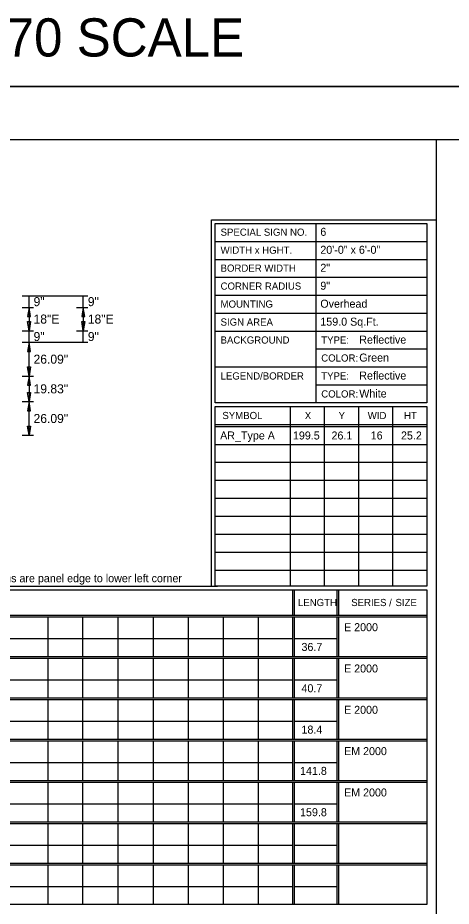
# Model space of a CAD drawing. Extents: x 2149934 to 2150188, y 145113 to 145238.
# Drawn here: x 2150108.5 to 2150136.4, y 145167.1 to 145224.4 of the extents above; entities that cross this region are included whole.
import ezdxf

# ---------------------------------------------------------------- set-up
doc = ezdxf.new("R2010")
doc.units = 0
for name, color, linetype in [('BORDER', 7, 'Continuous'), ('GSDIMS', 7, 'Continuous'), ('GSSHT', 7, 'Continuous'), ('Level 1', 7, 'Continuous'), ('PDF', 7, 'Continuous'), ('TEXT', 7, 'Continuous')]:
    doc.layers.add(name, color=color, linetype=linetype)

msp = doc.modelspace()

# ---------------------------------------------------------------- linework, layer by layer
at = {"layer": 'BORDER'}
for p, q in [((2150010.458, 145219.948), (2150174.061, 145219.948)), ((2150171.536, 145216.512), (2150017.557, 145216.512))]:
    msp.add_line(p, q, dxfattribs=at)
at = {"layer": 'GSDIMS'}
for p, q in [((2150108.758, 145206.445), (2150109.487, 145206.445)), ((2150108.758, 145206.445), (2150112.258, 145206.445)), ((2150109.195, 145205.695), (2150109.195, 145206.445)), ((2150112.258, 145206.445), (2150112.987, 145206.445)), ((2150112.695, 145205.695), (2150112.695, 145206.445)), ((2150108.758, 145205.695), (2150109.487, 145205.695)), ((2150108.758, 145205.695), (2150109.487, 145205.695)), ((2150109.195, 145205.695), (2150109.195, 145204.195)), ((2150112.258, 145205.695), (2150112.987, 145205.695)), ((2150112.258, 145205.695), (2150112.987, 145205.695)), ((2150112.695, 145205.695), (2150112.695, 145204.195)), ((2150108.758, 145204.195), (2150109.487, 145204.195)), ((2150108.758, 145204.195), (2150109.487, 145204.195)), ((2150109.195, 145203.445), (2150109.195, 145204.195)), ((2150112.258, 145204.195), (2150112.987, 145204.195)), ((2150112.258, 145204.195), (2150112.987, 145204.195)), ((2150112.695, 145203.445), (2150112.695, 145204.195)), ((2150108.758, 145203.445), (2150109.487, 145203.445)), ((2150108.758, 145203.445), (2150108.758, 145203.445)), ((2150108.758, 145203.445), (2150109.487, 145203.445)), ((2150108.758, 145203.445), (2150112.258, 145203.445)), ((2150109.195, 145201.271), (2150109.195, 145203.445)), ((2150112.258, 145203.445), (2150112.987, 145203.445)), ((2150108.758, 145201.271), (2150109.487, 145201.271)), ((2150108.758, 145201.271), (2150109.487, 145201.271)), ((2150109.195, 145201.271), (2150109.195, 145199.618)), ((2150108.758, 145199.618), (2150109.487, 145199.618)), ((2150108.758, 145199.618), (2150109.487, 145199.618)), ((2150109.195, 145197.445), (2150109.195, 145199.618)), ((2150108.758, 145197.445), (2150109.487, 145197.445)), ((2150108.758, 145197.445), (2150108.758, 145197.445))]:
    msp.add_line(p, q, dxfattribs=at)
for points in [[(2150109.195, 145205.695), (2150109.098, 145205.112), (2150109.293, 145205.112)], [(2150112.695, 145205.695), (2150112.598, 145205.112), (2150112.793, 145205.112)], [(2150109.195, 145204.195), (2150109.098, 145204.778), (2150109.293, 145204.778)], [(2150112.695, 145204.195), (2150112.598, 145204.778), (2150112.793, 145204.778)], [(2150109.195, 145203.445), (2150109.098, 145202.862), (2150109.293, 145202.862)], [(2150109.195, 145201.271), (2150109.098, 145201.854), (2150109.293, 145201.854)], [(2150109.195, 145201.271), (2150109.098, 145200.688), (2150109.293, 145200.688)], [(2150109.195, 145199.618), (2150109.098, 145200.202), (2150109.293, 145200.202)], [(2150109.195, 145199.618), (2150109.098, 145199.035), (2150109.293, 145199.035)], [(2150109.195, 145197.445), (2150109.098, 145198.028), (2150109.293, 145198.028)]]:
    msp.add_lwpolyline(points, close=True, dxfattribs=at)
at = {"layer": 'Level 1'}
for p, q in [((2150135.447, 145216.512), (2150135.447, 145124.606)), ((2150120.969, 145211.34), (2150135.447, 145211.34)), ((2150127.694, 145211.108), (2150127.694, 145199.537)), ((2150121.201, 145209.949), (2150134.843, 145209.949)), ((2150121.201, 145208.789), (2150134.843, 145208.789)), ((2150121.201, 145207.653), (2150134.843, 145207.653)), ((2150121.201, 145206.494), (2150134.843, 145206.494)), ((2150121.201, 145205.334), (2150134.843, 145205.334)), ((2150121.201, 145204.175), (2150134.843, 145204.175)), ((2150127.694, 145203.015), (2150134.843, 145203.015)), ((2150121.201, 145201.856), (2150134.843, 145201.856)), ((2150127.694, 145200.696), (2150134.843, 145200.696)), ((2150121.201, 145187.705), (2150121.201, 145199.305)), ((2150121.201, 145199.305), (2150134.843, 145199.305)), ((2150126.031, 145199.299), (2150126.031, 145198.14)), ((2150128.234, 145199.299), (2150128.234, 145198.14)), ((2150130.437, 145199.299), (2150130.437, 145198.14)), ((2150132.64, 145199.299), (2150132.64, 145198.14)), ((2150134.843, 145199.305), (2150134.843, 145187.705)), ((2150121.201, 145198.14), (2150134.843, 145198.14)), ((2150121.201, 145198.024), (2150134.843, 145198.024)), ((2150126.031, 145198.14), (2150126.031, 145187.705)), ((2150128.234, 145198.14), (2150128.234, 145187.705)), ((2150130.437, 145198.14), (2150130.437, 145187.705)), ((2150132.64, 145198.14), (2150132.64, 145187.705)), ((2150121.201, 145196.864), (2150134.843, 145196.864)), ((2150121.201, 145195.705), (2150134.843, 145195.705)), ((2150121.201, 145194.545), (2150134.843, 145194.545)), ((2150121.201, 145193.386), (2150134.843, 145193.386)), ((2150121.201, 145192.227), (2150134.843, 145192.227)), ((2150121.201, 145191.067), (2150134.843, 145191.067)), ((2150121.201, 145189.908), (2150134.843, 145189.908)), ((2150121.201, 145188.748), (2150134.843, 145188.748)), ((2150076.316, 145187.705), (2150121.342, 145187.705)), ((2150134.843, 145187.705), (2150121.201, 145187.705)), ((2150126.185, 145187.473), (2150126.185, 145185.849)), ((2150126.301, 145187.473), (2150126.301, 145185.849)), ((2150129.048, 145187.473), (2150129.048, 145185.849)), ((2150129.164, 145187.473), (2150129.164, 145185.849)), ((2150076.548, 145185.849), (2150134.843, 145185.849)), ((2150076.548, 145185.733), (2150134.843, 145185.733)), ((2150110.405, 145185.733), (2150110.405, 145183.183)), ((2150112.654, 145185.733), (2150112.654, 145183.183)), ((2150114.927, 145185.733), (2150114.927, 145183.183)), ((2150117.199, 145185.733), (2150117.199, 145183.183)), ((2150119.449, 145185.733), (2150119.449, 145183.183)), ((2150121.721, 145185.733), (2150121.721, 145183.183)), ((2150123.97, 145185.733), (2150123.97, 145183.183)), ((2150126.185, 145185.733), (2150126.185, 145183.183)), ((2150126.301, 145185.733), (2150126.301, 145183.183)), ((2150129.048, 145185.733), (2150129.048, 145183.183)), ((2150129.164, 145185.733), (2150129.164, 145183.183)), ((2150076.548, 145184.342), (2150126.185, 145184.342)), ((2150126.301, 145184.342), (2150129.048, 145184.342)), ((2150076.548, 145183.183), (2150134.843, 145183.183)), ((2150076.548, 145183.067), (2150134.843, 145183.067)), ((2150110.405, 145183.067), (2150110.405, 145180.516)), ((2150112.654, 145183.067), (2150112.654, 145180.516)), ((2150114.927, 145183.067), (2150114.927, 145180.516)), ((2150117.199, 145183.067), (2150117.199, 145180.516)), ((2150119.449, 145183.067), (2150119.449, 145180.516)), ((2150121.721, 145183.067), (2150121.721, 145180.516)), ((2150123.97, 145183.067), (2150123.97, 145180.516)), ((2150126.185, 145183.067), (2150126.185, 145180.516)), ((2150126.301, 145183.067), (2150126.301, 145180.516)), ((2150129.048, 145183.067), (2150129.048, 145180.516)), ((2150129.164, 145183.067), (2150129.164, 145180.516)), ((2150076.548, 145181.675), (2150126.185, 145181.675)), ((2150126.301, 145181.675), (2150129.048, 145181.675)), ((2150076.548, 145180.516), (2150134.843, 145180.516)), ((2150076.548, 145180.4), (2150134.843, 145180.4)), ((2150110.405, 145180.4), (2150110.405, 145177.849)), ((2150112.654, 145180.4), (2150112.654, 145177.849)), ((2150114.927, 145180.4), (2150114.927, 145177.849)), ((2150117.199, 145180.4), (2150117.199, 145177.849)), ((2150119.449, 145180.4), (2150119.449, 145177.849)), ((2150121.721, 145180.4), (2150121.721, 145177.849)), ((2150123.97, 145180.4), (2150123.97, 145177.849)), ((2150126.185, 145180.4), (2150126.185, 145177.849)), ((2150126.301, 145180.4), (2150126.301, 145177.849)), ((2150129.048, 145180.4), (2150129.048, 145177.849)), ((2150129.164, 145180.4), (2150129.164, 145177.849)), ((2150076.548, 145179.008), (2150126.185, 145179.008)), ((2150126.301, 145179.008), (2150129.048, 145179.008)), ((2150076.548, 145177.849), (2150134.843, 145177.849)), ((2150076.548, 145177.733), (2150134.843, 145177.733)), ((2150110.405, 145177.733), (2150110.405, 145175.182)), ((2150112.654, 145177.733), (2150112.654, 145175.182)), ((2150114.927, 145177.733), (2150114.927, 145175.182)), ((2150117.199, 145177.733), (2150117.199, 145175.182)), ((2150119.449, 145177.733), (2150119.449, 145175.182)), ((2150121.721, 145177.733), (2150121.721, 145175.182)), ((2150123.97, 145177.733), (2150123.97, 145175.182)), ((2150126.185, 145177.733), (2150126.185, 145175.182)), ((2150126.301, 145177.733), (2150126.301, 145175.182)), ((2150129.048, 145177.733), (2150129.048, 145175.182)), ((2150129.164, 145177.733), (2150129.164, 145175.182)), ((2150076.548, 145176.342), (2150126.185, 145176.342)), ((2150126.301, 145176.342), (2150129.048, 145176.342)), ((2150076.548, 145175.182), (2150134.843, 145175.182)), ((2150076.548, 145175.066), (2150134.843, 145175.066)), ((2150110.405, 145175.066), (2150110.405, 145172.515)), ((2150112.654, 145175.066), (2150112.654, 145172.515)), ((2150114.927, 145175.066), (2150114.927, 145172.515)), ((2150117.199, 145175.066), (2150117.199, 145172.515)), ((2150119.449, 145175.066), (2150119.449, 145172.515)), ((2150121.721, 145175.066), (2150121.721, 145172.515)), ((2150123.97, 145175.066), (2150123.97, 145172.515)), ((2150126.185, 145175.066), (2150126.185, 145172.515)), ((2150126.301, 145175.066), (2150126.301, 145172.515)), ((2150129.048, 145175.066), (2150129.048, 145172.515)), ((2150129.164, 145175.066), (2150129.164, 145172.515)), ((2150076.548, 145173.675), (2150126.185, 145173.675)), ((2150126.301, 145173.675), (2150129.048, 145173.675)), ((2150076.548, 145172.515), (2150134.843, 145172.515)), ((2150076.548, 145172.399), (2150134.843, 145172.399)), ((2150110.405, 145172.399), (2150110.405, 145169.849)), ((2150112.654, 145172.399), (2150112.654, 145169.849)), ((2150114.927, 145172.399), (2150114.927, 145169.849)), ((2150117.199, 145172.399), (2150117.199, 145169.849)), ((2150119.449, 145172.399), (2150119.449, 145169.849)), ((2150121.721, 145172.399), (2150121.721, 145169.849)), ((2150123.97, 145172.399), (2150123.97, 145169.849)), ((2150126.185, 145172.399), (2150126.185, 145169.849)), ((2150126.301, 145172.399), (2150126.301, 145169.849)), ((2150129.048, 145172.399), (2150129.048, 145169.849)), ((2150129.164, 145172.399), (2150129.164, 145169.849)), ((2150076.548, 145171.008), (2150126.185, 145171.008)), ((2150126.301, 145171.008), (2150129.048, 145171.008)), ((2150076.548, 145169.849), (2150134.843, 145169.849)), ((2150076.548, 145169.733), (2150134.843, 145169.733)), ((2150110.405, 145169.733), (2150110.405, 145167.182)), ((2150112.654, 145169.733), (2150112.654, 145167.182)), ((2150114.927, 145169.733), (2150114.927, 145167.182)), ((2150117.199, 145169.733), (2150117.199, 145167.182)), ((2150119.449, 145169.733), (2150119.449, 145167.182)), ((2150121.721, 145169.733), (2150121.721, 145167.182)), ((2150123.97, 145169.733), (2150123.97, 145167.182)), ((2150126.185, 145169.733), (2150126.185, 145167.182)), ((2150126.301, 145169.733), (2150126.301, 145167.182)), ((2150129.048, 145169.733), (2150129.048, 145167.182)), ((2150129.164, 145169.733), (2150129.164, 145167.182)), ((2150076.548, 145168.341), (2150126.185, 145168.341)), ((2150126.301, 145168.341), (2150129.048, 145168.341))]:
    msp.add_line(p, q, dxfattribs=at)
msp.add_lwpolyline([(2150120.969, 145187.705), (2150120.969, 145211.34)], dxfattribs=at)
for points in [[(2150121.201, 145211.108), (2150134.843, 145211.108), (2150134.843, 145199.537), (2150121.201, 145199.537)], [(2150076.548, 145187.473), (2150134.843, 145187.473), (2150134.843, 145167.182), (2150076.548, 145167.182)]]:
    msp.add_lwpolyline(points, close=True, dxfattribs=at)
at = {"layer": 'PDF'}
msp.add_lwpolyline([(2150010.458, 145114.088), (2150174.061, 145114.088), (2150174.061, 145219.948), (2150010.458, 145219.948)], close=True, dxfattribs=at)

# ---------------------------------------------------------------- texts
at = {"layer": 'GSDIMS'}
for s, p in [('9"', (2150109.487, 145205.778)), ('9"', (2150112.987, 145205.778)), ('18"E', (2150109.487, 145204.653)), ('18"E', (2150112.987, 145204.653)), ('9"', (2150109.487, 145203.528)), ('9"', (2150112.987, 145203.528)), ('26.09"', (2150109.487, 145202.066)), ('19.83"', (2150109.487, 145200.153)), ('26.09"', (2150109.487, 145198.24))]:
    msp.add_text(s, height=0.5833, dxfattribs=at).set_placement(p)
at = {"layer": 'GSSHT'}
for s, height, p in [('6', 0.517, (2150127.983, 145210.315)), ('Overhead', 0.5165, (2150127.983, 145205.679))]:
    msp.add_text(s, height=height, dxfattribs=at).set_placement(p)
at = {"layer": 'Level 1'}
for s, height, p in [('SPECIAL SIGN NO.', 0.46374, (2150121.549, 145210.32)), ('WIDTH x HGHT.', 0.46374, (2150121.549, 145209.16)), ('20\'-0" x 6\'-0"', 0.51652, (2150127.983, 145209.156)), ('BORDER WIDTH', 0.46374, (2150121.549, 145208.001)), ('2"', 0.5165, (2150127.983, 145207.997)), ('CORNER RADIUS', 0.46374, (2150121.549, 145206.841)), ('9"', 0.5165, (2150127.983, 145206.838)), ('MOUNTING', 0.4637, (2150121.549, 145205.682)), ('SIGN AREA', 0.4638, (2150121.549, 145204.522)), ('159.0 Sq.Ft.', 0.51652, (2150127.983, 145204.52)), ('BACKGROUND', 0.4637, (2150121.549, 145203.363)), ('TYPE:', 0.4637, (2150128.042, 145203.363)), ('Reflective', 0.5165, (2150130.494, 145203.361)), ('COLOR:', 0.4637, (2150128.042, 145202.203)), ('Green', 0.5165, (2150130.494, 145202.203)), ('LEGEND/BORDER', 0.46374, (2150121.549, 145201.044)), ('TYPE:', 0.4637, (2150128.042, 145201.044)), ('Reflective', 0.5165, (2150130.494, 145201.044)), ('COLOR:', 0.4637, (2150128.042, 145199.885)), ('White', 0.5165, (2150130.494, 145199.885)), ('SYMBOL', 0.4637, (2150121.665, 145198.493)), ('X', 0.464, (2150126.981, 145198.488)), ('Y', 0.464, (2150129.161, 145198.488)), ('WID', 0.4637, (2150131.04, 145198.488)), ('HT', 0.4637, (2150133.382, 145198.488)), ('AR_Type A', 0.5165, (2150121.52, 145197.177)), ('199.5', 0.5165, (2150126.216, 145197.177)), ('26.1', 0.5165, (2150128.704, 145197.177)), ('16', 0.5165, (2150131.233, 145197.177)), ('25.2', 0.5165, (2150133.185, 145197.177)), ('Letter locations are panel edge to lower left corner', 0.51652, (2150103.701, 145187.968)), ('LENGTH', 0.4638, (2150126.541, 145186.429)), ('LENGTH', 0.4638, (2150126.541, 145186.429)), ('SERIES /', 0.4638, (2150129.975, 145186.429)), ('SIZE', 0.4638, (2150132.832, 145186.429)), ('E 2000', 0.5165, (2150129.512, 145184.81)), ('36.7', 0.5165, (2150126.768, 145183.535)), ('E 2000', 0.5165, (2150129.512, 145182.145)), ('40.7', 0.5165, (2150126.768, 145180.87)), ('E 2000', 0.5165, (2150129.512, 145179.479)), ('18.4', 0.5165, (2150126.766, 145178.204)), ('EM 2000', 0.5165, (2150129.512, 145176.814)), ('141.8', 0.5165, (2150126.674, 145175.539)), ('EM 2000', 0.5165, (2150129.512, 145174.148)), ('159.8', 0.5165, (2150126.674, 145172.874))]:
    msp.add_text(s, height=height, dxfattribs=at).set_placement(p)
at = {"layer": 'TEXT'}
msp.add_text('BORDER AND REPORT 70 SCALE', height=2.46401, dxfattribs=at).set_placement((2150070.157, 145221.883))

doc.saveas('drawing.dxf')
